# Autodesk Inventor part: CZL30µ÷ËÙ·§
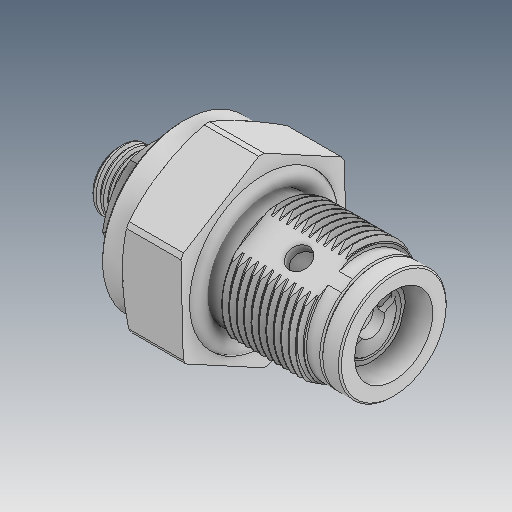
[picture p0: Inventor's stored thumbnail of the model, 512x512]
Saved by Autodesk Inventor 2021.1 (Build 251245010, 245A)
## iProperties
Created: 2019-12
Part Number: CZL30µ÷ËÙ·§
Material: Ogólny
Document SubType Name: Modeling
Designer: user
Density: 1 g/cm^3
Appearance: Domyślna
Author: user
Revision Number: ÈÎºÎ
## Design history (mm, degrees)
feature "ÊäÈë1"
feature "ÊäÈë2"
feature "ÊäÈë3"
feature "ÊäÈë4"
feature "ÊäÈë5"
feature "ÊäÈë6"
feature "ÊäÈë7"
node "Bryła1"
node "Bryła2"
node "Bryła3"
node "Bryła4"
node "Bryła5"
node "Bryła6"
node "Bryła7"
